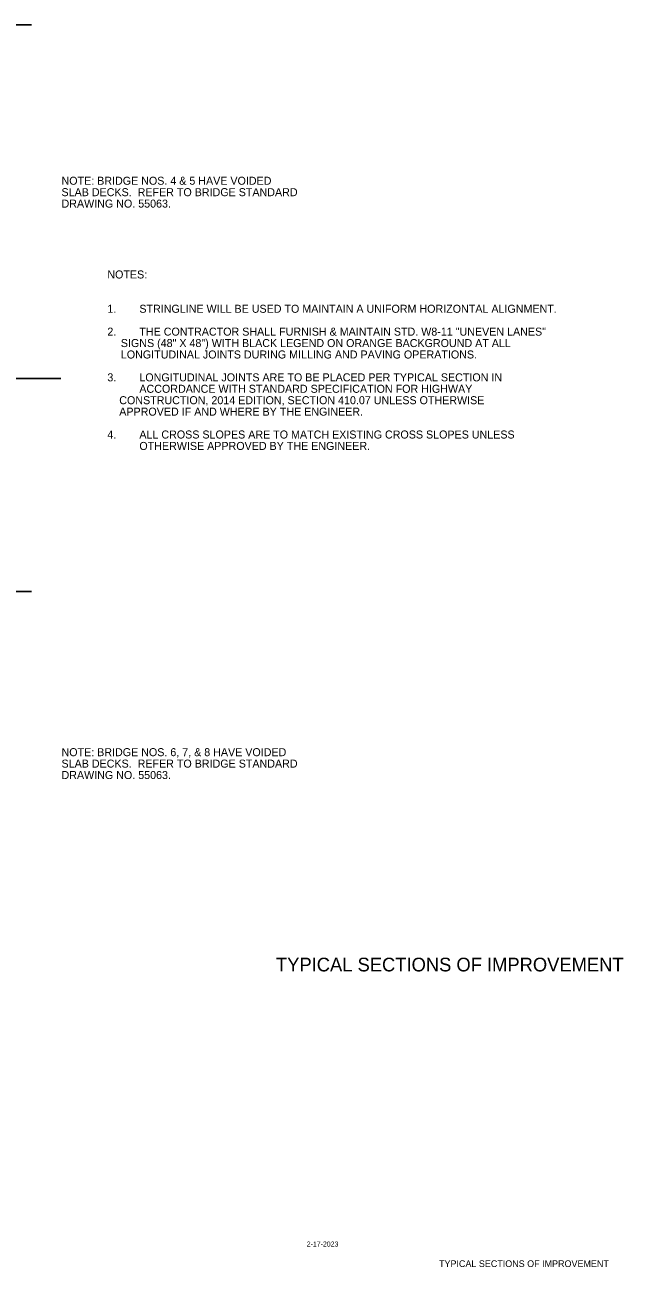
# Model space of a CAD drawing. Extents: x 549600 to 1930787, y -1955432 to 596640.
# Drawn here: x 552023 to 552546, y -1946941 to -1945854 of the extents above; entities that cross this region are included whole.
import ezdxf

# ---------------------------------------------------------------- set-up
doc = ezdxf.new("R2010")
doc.units = 0
for name, color, linetype in [('R_Border', 7, 'Continuous'), ('R_Border Notes', 7, 'Continuous'), ('R_Border Prem', 7, 'Continuous'), ('S_AREA_CALC', 7, 'Continuous')]:
    doc.layers.add(name, color=color, linetype=linetype)

msp = doc.modelspace()

# ---------------------------------------------------------------- linework, layer by layer
at = {"layer": 'R_Border'}
msp.add_line((550992.9, -1946163.5), (552054.2, -1946163.5), dxfattribs=at)
at = {"layer": 'S_AREA_CALC'}
for p, q in [((552028.5, -1945854), (552002, -1945854)), ((552028.5, -1946349.8), (552002, -1946349.8))]:
    msp.add_line(p, q, dxfattribs=at)

# ---------------------------------------------------------------- texts
at = {"layer": 'R_Border'}
msp.add_text('TYPICAL SECTIONS OF IMPROVEMENT', height=12, rotation=360, dxfattribs=at).set_placement((552242.3, -1946682.1))
at = {"layer": 'R_Border Notes'}
for s, p in [('SLAB DECKS.  REFER TO BRIDGE STANDARD', (552054.7, -1946003.9)), ('NOTE: BRIDGE NOS. 4 & 5 HAVE VOIDED', (552054.7, -1945993.9)), ('DRAWING NO. 55063.', (552054.7, -1946013.9)), ('NOTES: ', (552094.8, -1946075.9)), ('1.', (552094.8, -1946105.9)), ('STRINGLINE WILL BE USED TO MAINTAIN A UNIFORM HORIZONTAL ALIGNMENT.', (552122.8, -1946105.9)), ('2.', (552094.8, -1946125.9)), ('THE CONTRACTOR SHALL FURNISH & MAINTAIN STD. W8-11 "UNEVEN LANES" ', (552122.8, -1946125.9)), ('    SIGNS (48" X 48") WITH BLACK LEGEND ON ORANGE BACKGROUND AT ALL ', (552096.2, -1946135.9)), ('    LONGITUDINAL JOINTS DURING MILLING AND PAVING OPERATIONS.', (552096.2, -1946145.9)), ('3.', (552094.8, -1946165.9)), ('LONGITUDINAL JOINTS ARE TO BE PLACED PER TYPICAL SECTION IN ', (552122.8, -1946165.9)), ('ACCORDANCE WITH STANDARD SPECIFICATION FOR HIGHWAY', (552122.8, -1946175.9)), ('    CONSTRUCTION, 2014 EDITION, SECTION 410.07 UNLESS OTHERWISE', (552094.8, -1946185.9)), ('    APPROVED IF AND WHERE BY THE ENGINEER.', (552094.8, -1946195.9)), ('4.', (552094.8, -1946215.9)), ('ALL CROSS SLOPES ARE TO MATCH EXISTING CROSS SLOPES UNLESS ', (552122.8, -1946215.9)), ('OTHERWISE APPROVED BY THE ENGINEER.', (552122.8, -1946225.9)), ('SLAB DECKS.  REFER TO BRIDGE STANDARD', (552054.7, -1946503.8)), ('NOTE: BRIDGE NOS. 6, 7, & 8 HAVE VOIDED', (552054.7, -1946493.8)), ('DRAWING NO. 55063.', (552054.7, -1946513.8))]:
    msp.add_text(s, height=7, dxfattribs=at).set_placement(p)
at = {"layer": 'R_Border Prem'}
msp.add_text('2-17-2023', height=4.4, dxfattribs=at).set_placement((552269.2, -1946922.8))
msp.add_text('TYPICAL SECTIONS OF IMPROVEMENT', height=5.862, rotation=360, dxfattribs=at).set_placement((552384.9, -1946940.7))

doc.saveas('drawing.dxf')
